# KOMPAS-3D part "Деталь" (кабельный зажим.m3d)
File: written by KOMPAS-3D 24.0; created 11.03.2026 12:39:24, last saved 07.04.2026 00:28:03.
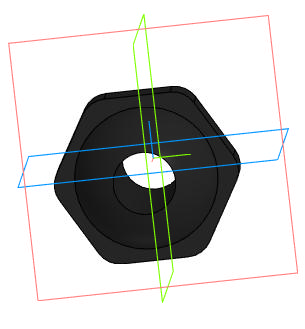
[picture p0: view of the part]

Document properties: Автор: R2D2; Полное имя файла: E:\Работа\Зайцев\Солянка\VSR1-13V-PED-F Клапан запорно-регулирующий DN.ru\DN15\DN15 Kv0.16\исходные материалы\кабельный зажим.m3d

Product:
- Part/product: Деталь
    Масса: 0.106559

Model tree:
1. Эскиз:1
2. Элемент вращения:1
     Угол 1 = 360
3. Эскиз:2  (with: Грань.Элемент вращения:1)
4. Элемент выдавливания:1
     Расстояние 2 = 10
5. Эскиз:3  (with: Грань.Элемент вращения:1)
6. Элемент выдавливания:2  (with: Грань.Элемент вращения:1)
     Расстояние 2 = 8
7. Эскиз:4  (with: Грань.Элемент вращения:1)
8. Элемент выдавливания:3
     Расстояние 2 = 42
9. Скругление:1  (with: Ребро.Элемент выдавливания:1)
     Радиус = 5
